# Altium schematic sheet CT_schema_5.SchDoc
size 368 x 245 mm
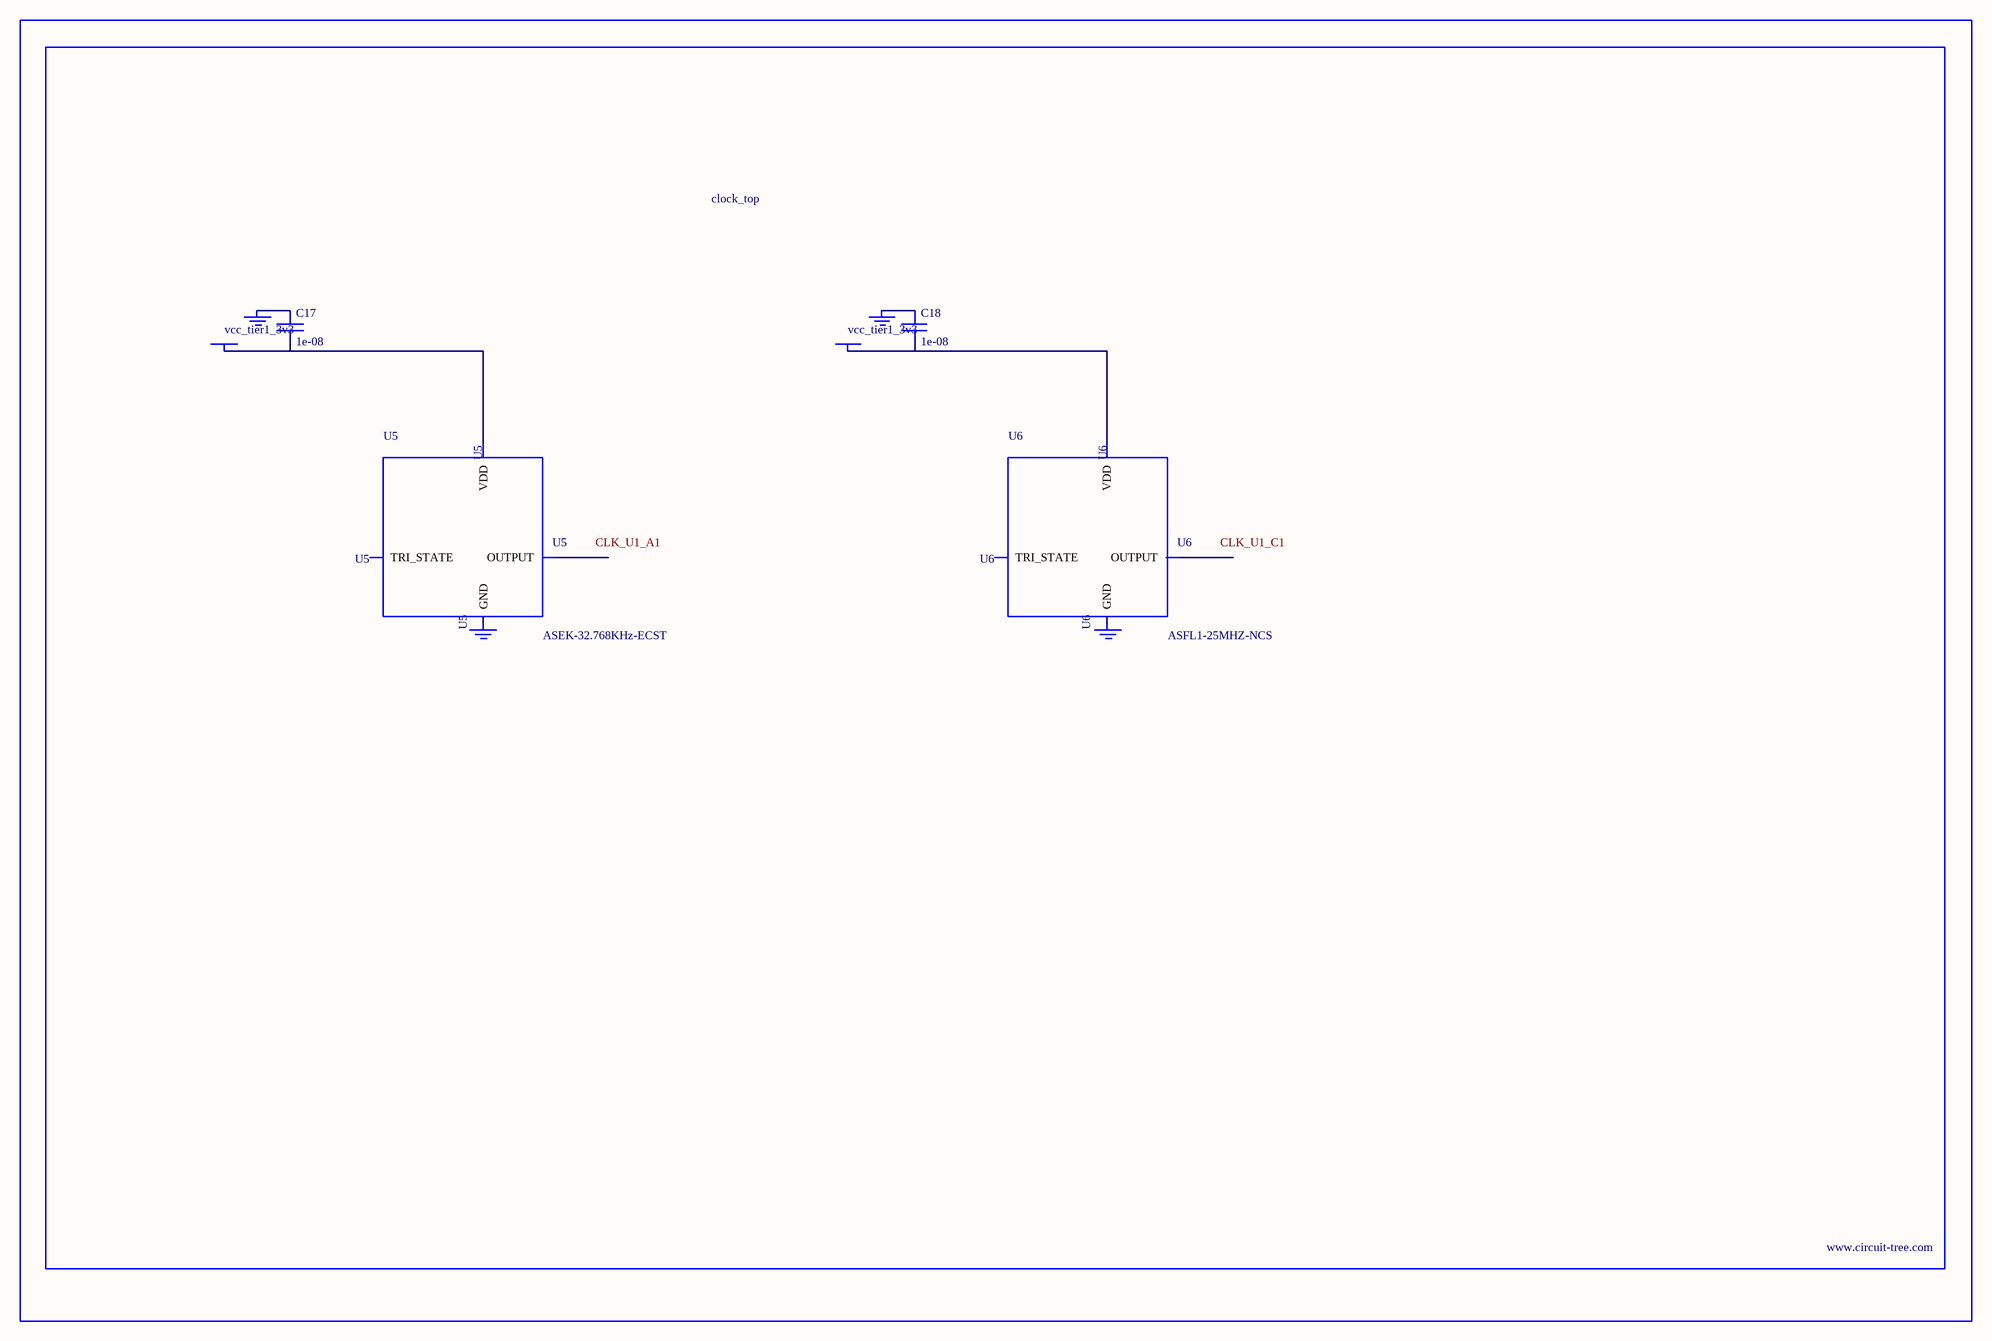
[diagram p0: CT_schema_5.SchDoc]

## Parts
BORDER4  (no value)
C17  1e-08  [C0402]
C18  1e-08  [C0402]
GND_INSTANCE_4_0  (no value)
GND_INSTANCE_4_1  (no value)
GND_INSTANCE_4_2  (no value)
GND_INSTANCE_4_3  (no value)
POWER_INSTANCE_4_0  vcc_tier1_3v3
POWER_INSTANCE_4_1  vcc_tier1_3v3
U5  ASEK-32.768KHz-ECST  [ASEK]
U6  ASFL1-25MHZ-NCS  [ASFL1]

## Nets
NetC17_1: C17.1 GND_INSTANCE_4_0.0(GND)
NetC17_2: C17.2 POWER_INSTANCE_4_0.0(PWR) U5.4(VDD)
NetC18_1: C18.1 GND_INSTANCE_4_2.0(GND)
NetC18_2: C18.2 POWER_INSTANCE_4_1.0(PWR) U6.4(VDD)

Not connected (* = marked no-connect by the designer): GND_INSTANCE_4_1 0(GND); GND_INSTANCE_4_3 0(GND); U5 1(TRI_STATE) 2(GND) 3(OUTPUT); U6 1(TRI_STATE) 2(GND) 3(OUTPUT)

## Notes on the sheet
- Labels drawn without touching a wire or pin: CLK_U1_A1, CLK_U1_C1

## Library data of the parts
BORDER4 = BORDER_PAGE4
C17 C18 = C0402C103K3RAC
GND_INSTANCE_4_0-GND_INSTANCE_4_3 = GND
POWER_INSTANCE_4_0 POWER_INSTANCE_4_1 = PWR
